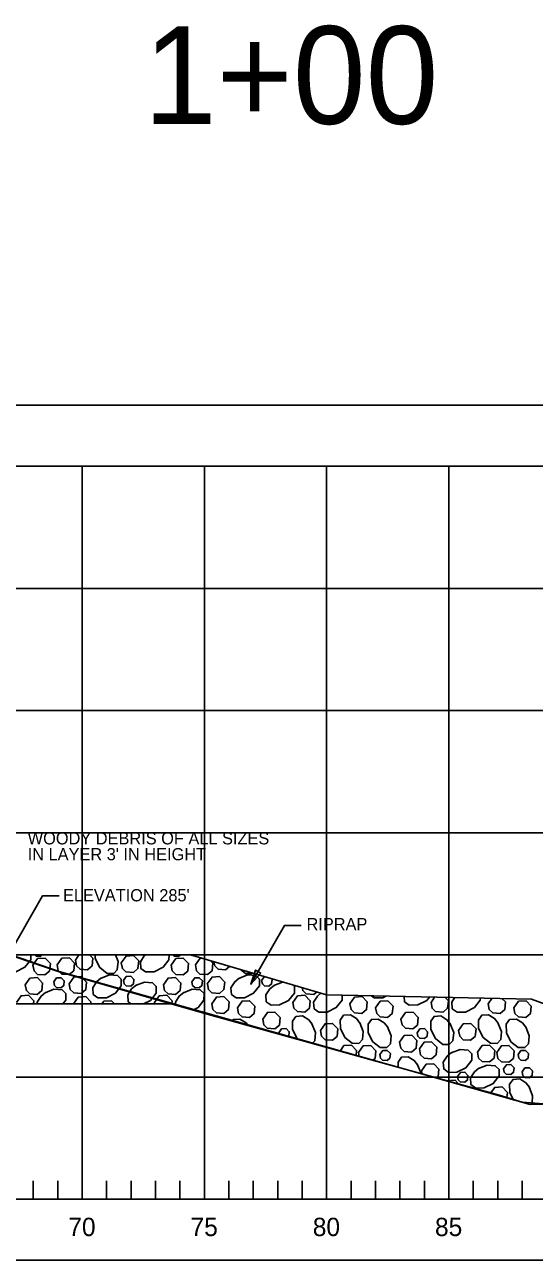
# Model space of a CAD drawing. Extents: x 1578769 to 1579225, y 724002 to 724828.
# Drawn here: x 1578892.8 to 1578913.6, y 724249.6 to 724300.2 of the extents above; entities that cross this region are included whole.
import ezdxf

# ---------------------------------------------------------------- set-up
doc = ezdxf.new("R2010")
doc.units = 0
for name, color, linetype in [('1', 7, 'Continuous'), ('Default', 7, 'Continuous'), ('Old_Level_1', 7, 'Continuous'), ('Old_Level_41', 7, 'Continuous'), ('Old_Level_42', 7, 'Continuous'), ('R_Exist Surface', 7, 'Continuous'), ('R_Rip-Rap', 7, 'Continuous')]:
    doc.layers.add(name, color=color, linetype=linetype)

msp = doc.modelspace()

# ---------------------------------------------------------------- linework, layer by layer
at = {"layer": '1'}
for points in [[(1578892.141, 724262.141), (1578893.509, 724264.554), (1578894.194, 724264.554)], [(1578902.042, 724260.935), (1578903.41, 724263.349), (1578904.095, 724263.349)]]:
    msp.add_lwpolyline(points, dxfattribs=at)
msp.add_lwpolyline([(1578902.442, 724261.398), (1578902.042, 724260.935), (1578902.233, 724261.516)], close=True, dxfattribs=at)
at = {"layer": 'Default'}
msp.add_line((1578825.136, 724252.141), (1579225.136, 724252.141), dxfattribs=at)
msp.add_lwpolyline([(1578826.025, 724272.503), (1578843.356, 724272.54), (1578848.216, 724272.563), (1578852.656, 724272.595), (1578873.806, 724272.679), (1578875.706, 724271.556), (1578889.515, 724263.067), (1578894.196, 724261.454), (1578913.456, 724256.023), (1578914.486, 724256.05), (1578915.035, 724256.065), (1578992.496, 724256.633), (1578992.515, 724256.633), (1578992.566, 724256.634), (1578992.736, 724256.639), (1578993.706, 724256.668), (1579090.356, 724259.528), (1579113.086, 724262.229), (1579131.176, 724264.398), (1579155.015, 724266.722), (1579177.006, 724269.229), (1579191.525, 724270.885)], dxfattribs=at)
at = {"layer": 'Old_Level_1'}
for points in [[(1578820.135, 724284.641), (1578927.635, 724284.641), (1578927.635, 724249.641), (1578820.135, 724249.641)], [(1578825.135, 724282.141), (1578925.135, 724282.141), (1578925.135, 724252.141), (1578825.135, 724252.141)]]:
    msp.add_lwpolyline(points, close=True, dxfattribs=at)
at = {"layer": 'Old_Level_41'}
for p, q in [((1578895.135, 724282.141), (1578895.135, 724252.141)), ((1578900.135, 724252.141), (1578900.135, 724282.141)), ((1578905.135, 724282.141), (1578905.135, 724252.141)), ((1578910.135, 724252.141), (1578910.135, 724282.141))]:
    msp.add_line(p, q, dxfattribs=at)
for points in [[(1578925.135, 724277.141), (1578825.135, 724277.141)], [(1578925.135, 724272.141), (1578825.135, 724272.141)], [(1578825.135, 724267.141), (1578925.135, 724267.141)], [(1578925.135, 724262.141), (1578825.135, 724262.141)], [(1578825.135, 724257.141), (1578925.135, 724257.141)]]:
    msp.add_lwpolyline(points, dxfattribs=at)
at = {"layer": 'Old_Level_42'}
for p, q in [((1578893.135, 724252.891), (1578893.135, 724252.141)), ((1578894.135, 724252.891), (1578894.135, 724252.141)), ((1578896.135, 724252.891), (1578896.135, 724252.141)), ((1578897.135, 724252.891), (1578897.135, 724252.141)), ((1578898.135, 724252.891), (1578898.135, 724252.141)), ((1578899.135, 724252.891), (1578899.135, 724252.141)), ((1578901.135, 724252.891), (1578901.135, 724252.141)), ((1578902.135, 724252.891), (1578902.135, 724252.141)), ((1578903.135, 724252.891), (1578903.135, 724252.141)), ((1578904.135, 724252.891), (1578904.135, 724252.141)), ((1578906.135, 724252.891), (1578906.135, 724252.141)), ((1578907.135, 724252.891), (1578907.135, 724252.141)), ((1578908.135, 724252.891), (1578908.135, 724252.141)), ((1578909.135, 724252.891), (1578909.135, 724252.141)), ((1578911.135, 724252.891), (1578911.135, 724252.141)), ((1578912.135, 724252.891), (1578912.135, 724252.141)), ((1578913.135, 724252.891), (1578913.135, 724252.141))]:
    msp.add_line(p, q, dxfattribs=at)
at = {"layer": 'R_Exist Surface'}
msp.add_lwpolyline([(1578826.062, 724272.509), (1578843.255, 724272.529), (1578855.204, 724272.649), (1578859.177, 724272.597), (1578872.167, 724272.617), (1578873.087, 724272.657), (1578874.163, 724272.457), (1578875.161, 724271.898), (1578886.138, 724265.225), (1578890.363, 724262.7), (1578891.18, 724262.468), (1578894.233, 724261.427), (1578900.147, 724259.744), (1578907.197, 724257.773), (1578912.15, 724256.411), (1578913.135, 724256.113), (1578914.178, 724256.033), (1578918.136, 724256.056), (1578925.136, 724256.105)], dxfattribs=at)
at = {"layer": 'R_Rip-Rap'}
for p, q in [((1578899.572, 724262.141), (1578888.226, 724262.141)), ((1578894.858, 724261.93), (1578895.006, 724262.141)), ((1578905.135, 724260.499), (1578899.572, 724262.141)), ((1578902.478, 724261.094), (1578902.588, 724261.251)), ((1578888.226, 724260.134), (1578898.778, 724260.134)), ((1578894.784, 724260.134), (1578894.783, 724260.142)), ((1578898.111, 724260.134), (1578898.099, 724260.196)), ((1578913.512, 724260.324), (1578905.135, 724260.499)), ((1578909.406, 724260.196), (1578909.554, 724260.407)), ((1578911.743, 724260.142), (1578911.894, 724260.357)), ((1578924.962, 724256.104), (1578913.512, 724260.324)), ((1578903.192, 724258.893), (1578903.181, 724258.95)), ((1578906.473, 724257.981), (1578906.441, 724258.143)), ((1578909.042, 724257.267), (1578909.018, 724257.391))]:
    msp.add_line(p, q, dxfattribs=at)
for points in [[(1578893.036, 724262.141), (1578893.033, 724261.938), (1578892.795, 724261.634), (1578892.427, 724261.45), (1578892.08, 724261.444), (1578891.885, 724261.582), (1578891.866, 724261.859), (1578892.025, 724262.106), (1578892.068, 724262.141)], [(1578893.502, 724262.141), (1578893.43, 724262.08), (1578893.248, 724262.094), (1578893.2, 724262.141)], [(1578895.434, 724262.141), (1578895.57, 724262), (1578895.539, 724261.69), (1578895.35, 724261.533), (1578895.047, 724261.555), (1578894.904, 724261.693), (1578894.858, 724261.93)], [(1578896.493, 724262.141), (1578896.603, 724261.864), (1578896.574, 724261.533), (1578896.425, 724261.377), (1578896.157, 724261.382), (1578895.853, 724261.62), (1578895.669, 724261.988), (1578895.666, 724262.141)], [(1578896.737, 724261.82), (1578896.929, 724262.093), (1578897.236, 724262.111), (1578897.449, 724261.89), (1578897.418, 724261.58), (1578897.229, 724261.422), (1578896.926, 724261.444), (1578896.784, 724261.582), (1578896.737, 724261.82)], [(1578898.69, 724262.141), (1578898.686, 724261.938), (1578898.448, 724261.634), (1578898.08, 724261.45), (1578897.733, 724261.444), (1578897.538, 724261.582), (1578897.52, 724261.859), (1578897.678, 724262.106), (1578897.722, 724262.141)], [(1578899.156, 724262.141), (1578899.083, 724262.08), (1578898.902, 724262.094), (1578898.853, 724262.141)], [(1578893.122, 724261.719), (1578893.314, 724261.992), (1578893.621, 724262.009), (1578893.834, 724261.788), (1578893.803, 724261.478), (1578893.614, 724261.321), (1578893.311, 724261.343), (1578893.168, 724261.481), (1578893.122, 724261.718)], [(1578894.113, 724261.73), (1578894.305, 724262.003), (1578894.612, 724262.021), (1578894.825, 724261.8), (1578894.794, 724261.49), (1578894.605, 724261.332), (1578894.302, 724261.354), (1578894.159, 724261.492), (1578894.113, 724261.73)], [(1578898.775, 724261.719), (1578898.968, 724261.992), (1578899.274, 724262.009), (1578899.487, 724261.788), (1578899.457, 724261.478), (1578899.267, 724261.321), (1578898.964, 724261.343), (1578898.822, 724261.481), (1578898.776, 724261.718)], [(1578899.766, 724261.73), (1578899.959, 724262.003), (1578900.025, 724262.007)], [(1578900.379, 724261.902), (1578900.478, 724261.8), (1578900.448, 724261.49), (1578900.258, 724261.332), (1578899.955, 724261.354), (1578899.813, 724261.492), (1578899.767, 724261.73)], [(1578901.168, 724261.67), (1578901.003, 724261.533), (1578900.7, 724261.555), (1578900.558, 724261.693), (1578900.525, 724261.859)], [(1578892.807, 724260.918), (1578892.999, 724261.192), (1578893.306, 724261.209), (1578893.519, 724260.988), (1578893.488, 724260.678), (1578893.299, 724260.521), (1578892.996, 724260.543), (1578892.853, 724260.681), (1578892.807, 724260.918)], [(1578893.972, 724261.031), (1578894.088, 724261.195), (1578894.272, 724261.205), (1578894.4, 724261.073), (1578894.381, 724260.887), (1578894.268, 724260.792), (1578894.086, 724260.805), (1578894, 724260.888), (1578893.973, 724261.031)], [(1578894.602, 724260.96), (1578894.794, 724261.233), (1578895.101, 724261.251), (1578895.314, 724261.03), (1578895.283, 724260.72), (1578895.094, 724260.562), (1578894.791, 724260.584), (1578894.648, 724260.722), (1578894.602, 724260.96)], [(1578895.891, 724261.178), (1578896.25, 724261.321), (1578896.58, 724261.292), (1578896.737, 724261.143), (1578896.732, 724260.875), (1578896.494, 724260.571), (1578896.126, 724260.387), (1578895.779, 724260.381), (1578895.584, 724260.52), (1578895.566, 724260.796), (1578895.724, 724261.043), (1578895.905, 724261.188)], [(1578896.825, 724261.094), (1578896.94, 724261.258), (1578897.124, 724261.268), (1578897.252, 724261.136), (1578897.233, 724260.95), (1578897.12, 724260.855), (1578896.938, 724260.868), (1578896.853, 724260.951), (1578896.825, 724261.094)], [(1578898.46, 724260.918), (1578898.653, 724261.192), (1578898.959, 724261.209), (1578899.172, 724260.988), (1578899.142, 724260.678), (1578898.952, 724260.521), (1578898.649, 724260.543), (1578898.507, 724260.681), (1578898.461, 724260.918)], [(1578899.626, 724261.031), (1578899.741, 724261.195), (1578899.925, 724261.205), (1578900.053, 724261.073), (1578900.035, 724260.887), (1578899.921, 724260.792), (1578899.739, 724260.805), (1578899.654, 724260.888), (1578899.626, 724261.031)], [(1578900.255, 724260.96), (1578900.447, 724261.233), (1578900.754, 724261.251), (1578900.967, 724261.03), (1578900.936, 724260.72), (1578900.747, 724260.562), (1578900.444, 724260.584), (1578900.302, 724260.722), (1578900.256, 724260.96)], [(1578901.544, 724261.178), (1578901.904, 724261.321), (1578902.234, 724261.292), (1578902.391, 724261.143), (1578902.386, 724260.875), (1578902.148, 724260.571), (1578901.78, 724260.387), (1578901.433, 724260.381), (1578901.238, 724260.52), (1578901.219, 724260.796), (1578901.377, 724261.043), (1578901.559, 724261.188)], [(1578902.097, 724261.396), (1578902.079, 724261.377), (1578901.811, 724261.382), (1578901.609, 724261.54)], [(1578902.876, 724261.166), (1578902.905, 724261.136), (1578902.887, 724260.95), (1578902.773, 724260.855), (1578902.591, 724260.868), (1578902.506, 724260.951), (1578902.478, 724261.094)], [(1578893.301, 724260.134), (1578893.296, 724260.21), (1578893.454, 724260.457), (1578893.636, 724260.602)], [(1578893.621, 724260.593), (1578893.98, 724260.735), (1578894.311, 724260.707), (1578894.467, 724260.558), (1578894.462, 724260.29), (1578894.34, 724260.134)], [(1578897.143, 724260.134), (1578897.016, 724260.225), (1578896.997, 724260.501), (1578897.156, 724260.748), (1578897.337, 724260.893)], [(1578897.322, 724260.883), (1578897.682, 724261.026), (1578898.012, 724260.997), (1578898.169, 724260.848), (1578898.164, 724260.58), (1578897.926, 724260.276), (1578897.642, 724260.134)], [(1578898.958, 724260.083), (1578898.949, 724260.21), (1578899.108, 724260.457), (1578899.289, 724260.602)], [(1578899.275, 724260.593), (1578899.634, 724260.735), (1578899.964, 724260.707), (1578900.121, 724260.558), (1578900.116, 724260.29), (1578899.878, 724259.986), (1578899.668, 724259.881)], [(1578903.764, 724260.904), (1578903.822, 724260.848), (1578903.817, 724260.58), (1578903.579, 724260.276), (1578903.211, 724260.092), (1578902.864, 724260.086), (1578902.669, 724260.225), (1578902.651, 724260.501), (1578902.809, 724260.748), (1578902.99, 724260.893)], [(1578902.976, 724260.883), (1578903.335, 724261.026), (1578903.356, 724261.024)], [(1578904.725, 724260.62), (1578904.606, 724260.521), (1578904.303, 724260.543), (1578904.16, 724260.681), (1578904.138, 724260.793)], [(1578892.446, 724260.196), (1578892.638, 724260.469), (1578892.944, 724260.486), (1578893.158, 724260.265), (1578893.144, 724260.134)], [(1578894.783, 724260.142), (1578894.975, 724260.415), (1578895.281, 724260.433), (1578895.495, 724260.212), (1578895.487, 724260.134)], [(1578895.945, 724260.134), (1578896.025, 724260.248), (1578896.332, 724260.265), (1578896.458, 724260.134)], [(1578898.099, 724260.196), (1578898.291, 724260.469), (1578898.598, 724260.486), (1578898.811, 724260.265), (1578898.797, 724260.128)], [(1578900.436, 724260.142), (1578900.628, 724260.415), (1578900.935, 724260.433), (1578901.148, 724260.212), (1578901.117, 724259.902), (1578900.928, 724259.744), (1578900.625, 724259.766), (1578900.483, 724259.904), (1578900.436, 724260.142)], [(1578901.486, 724259.975), (1578901.678, 724260.248), (1578901.985, 724260.265), (1578902.198, 724260.044), (1578902.167, 724259.735), (1578901.978, 724259.577), (1578901.675, 724259.599), (1578901.533, 724259.737), (1578901.486, 724259.975)], [(1578903.752, 724260.196), (1578903.945, 724260.469), (1578904.251, 724260.486), (1578904.464, 724260.265), (1578904.434, 724259.956), (1578904.244, 724259.798), (1578903.941, 724259.82), (1578903.799, 724259.958), (1578903.753, 724260.196)], [(1578905.773, 724260.486), (1578905.769, 724260.29), (1578905.531, 724259.986), (1578905.163, 724259.802), (1578904.816, 724259.795), (1578904.621, 724259.934), (1578904.603, 724260.21), (1578904.761, 724260.457), (1578904.9, 724260.569)], [(1578906.09, 724260.142), (1578906.282, 724260.415), (1578906.588, 724260.433), (1578906.801, 724260.212), (1578906.771, 724259.902), (1578906.581, 724259.744), (1578906.278, 724259.766), (1578906.136, 724259.904), (1578906.09, 724260.142)], [(1578907.556, 724260.448), (1578907.433, 724260.387), (1578907.086, 724260.381), (1578906.974, 724260.461)], [(1578907.14, 724259.975), (1578907.332, 724260.248), (1578907.638, 724260.265), (1578907.852, 724260.044), (1578907.821, 724259.735), (1578907.631, 724259.577), (1578907.329, 724259.599), (1578907.186, 724259.737), (1578907.14, 724259.975)], [(1578909.338, 724260.411), (1578909.232, 724260.276), (1578908.865, 724260.092), (1578908.518, 724260.086), (1578908.323, 724260.225), (1578908.309, 724260.433)], [(1578909.99, 724260.397), (1578910.118, 724260.265), (1578910.087, 724259.956), (1578909.898, 724259.798), (1578909.595, 724259.82), (1578909.452, 724259.958), (1578909.406, 724260.196)], [(1578911.424, 724260.367), (1578911.423, 724260.29), (1578911.185, 724259.986), (1578910.817, 724259.802), (1578910.47, 724259.795), (1578910.275, 724259.934), (1578910.256, 724260.21), (1578910.371, 724260.389)], [(1578912.323, 724260.348), (1578912.455, 724260.212), (1578912.424, 724259.902), (1578912.235, 724259.744), (1578911.932, 724259.766), (1578911.789, 724259.904), (1578911.743, 724260.142)], [(1578912.793, 724259.975), (1578912.985, 724260.248), (1578913.292, 724260.265), (1578913.505, 724260.044), (1578913.474, 724259.735), (1578913.285, 724259.577), (1578912.982, 724259.599), (1578912.84, 724259.737), (1578912.793, 724259.975)], [(1578900.366, 724259.683), (1578900.453, 724259.689), (1578900.537, 724259.635)], [(1578902.521, 724259.51), (1578902.713, 724259.783), (1578903.019, 724259.801), (1578903.233, 724259.58), (1578903.202, 724259.27), (1578903.012, 724259.112), (1578902.71, 724259.134), (1578902.567, 724259.273), (1578902.521, 724259.51)], [(1578903.983, 724258.672), (1578903.93, 724258.714), (1578903.746, 724259.082), (1578903.74, 724259.429), (1578903.878, 724259.624), (1578904.155, 724259.642), (1578904.402, 724259.484), (1578904.546, 724259.303)], [(1578906.489, 724259.364), (1578906.632, 724259.004), (1578906.603, 724258.674), (1578906.454, 724258.517), (1578906.186, 724258.522), (1578905.882, 724258.76), (1578905.698, 724259.128), (1578905.692, 724259.475), (1578905.83, 724259.67), (1578906.107, 724259.689), (1578906.354, 724259.531), (1578906.498, 724259.349)], [(1578908.174, 724259.51), (1578908.366, 724259.783), (1578908.673, 724259.801), (1578908.886, 724259.58), (1578908.855, 724259.27), (1578908.666, 724259.112), (1578908.363, 724259.134), (1578908.221, 724259.273), (1578908.174, 724259.51)], [(1578910.19, 724259.317), (1578910.333, 724258.958), (1578910.304, 724258.628), (1578910.155, 724258.471), (1578909.887, 724258.476), (1578909.583, 724258.714), (1578909.399, 724259.082), (1578909.393, 724259.429), (1578909.532, 724259.624), (1578909.808, 724259.642), (1578910.055, 724259.484), (1578910.2, 724259.303)], [(1578912.143, 724259.364), (1578912.285, 724259.004), (1578912.257, 724258.674), (1578912.107, 724258.517), (1578911.84, 724258.522), (1578911.535, 724258.76), (1578911.351, 724259.128), (1578911.345, 724259.475), (1578911.484, 724259.67), (1578911.76, 724259.689), (1578912.007, 724259.531), (1578912.152, 724259.349)], [(1578901.269, 724259.431), (1578901.316, 724259.496), (1578901.592, 724259.515), (1578901.839, 724259.356), (1578901.926, 724259.247)], [(1578903.181, 724258.95), (1578903.296, 724259.114), (1578903.48, 724259.125), (1578903.608, 724258.992), (1578903.589, 724258.806), (1578903.568, 724258.788)], [(1578904.537, 724259.317), (1578904.68, 724258.958), (1578904.651, 724258.628), (1578904.545, 724258.516)], [(1578904.882, 724259.045), (1578905.074, 724259.319), (1578905.381, 724259.336), (1578905.594, 724259.115), (1578905.563, 724258.805), (1578905.374, 724258.648), (1578905.071, 724258.67), (1578904.929, 724258.808), (1578904.882, 724259.045)], [(1578907.628, 724259.189), (1578907.77, 724258.83), (1578907.742, 724258.5), (1578907.593, 724258.343), (1578907.325, 724258.348), (1578907.021, 724258.586), (1578906.837, 724258.954), (1578906.831, 724259.301), (1578906.969, 724259.496), (1578907.245, 724259.515), (1578907.493, 724259.356), (1578907.637, 724259.175)], [(1578908.834, 724258.95), (1578908.949, 724259.114), (1578909.133, 724259.125), (1578909.261, 724258.992), (1578909.243, 724258.806), (1578909.129, 724258.712), (1578908.947, 724258.725), (1578908.862, 724258.808), (1578908.834, 724258.95)], [(1578910.536, 724259.045), (1578910.728, 724259.319), (1578911.034, 724259.336), (1578911.248, 724259.115), (1578911.217, 724258.805), (1578911.027, 724258.648), (1578910.724, 724258.67), (1578910.582, 724258.808), (1578910.536, 724259.045)], [(1578913.281, 724259.189), (1578913.424, 724258.83), (1578913.395, 724258.5), (1578913.246, 724258.343), (1578912.978, 724258.348), (1578912.674, 724258.586), (1578912.49, 724258.954), (1578912.484, 724259.301), (1578912.623, 724259.496), (1578912.899, 724259.515), (1578913.146, 724259.356), (1578913.291, 724259.175)], [(1578908.12, 724258.561), (1578908.312, 724258.834), (1578908.619, 724258.852), (1578908.832, 724258.631), (1578908.801, 724258.321), (1578908.612, 724258.164), (1578908.309, 724258.186), (1578908.167, 724258.324), (1578908.121, 724258.561)], [(1578908.932, 724258.29), (1578909.124, 724258.563), (1578909.431, 724258.581), (1578909.644, 724258.36), (1578909.613, 724258.05), (1578909.424, 724257.892), (1578909.121, 724257.914), (1578908.978, 724258.052), (1578908.932, 724258.29)], [(1578905.683, 724258.2), (1578905.843, 724258.428), (1578906.15, 724258.445), (1578906.363, 724258.224), (1578906.342, 724258.017)], [(1578906.441, 724258.143), (1578906.633, 724258.416), (1578906.94, 724258.434), (1578907.153, 724258.213), (1578907.122, 724257.903), (1578907.03, 724257.826)], [(1578907.315, 724258.059), (1578907.43, 724258.222), (1578907.614, 724258.233), (1578907.742, 724258.1), (1578907.724, 724257.915), (1578907.61, 724257.82), (1578907.428, 724257.833), (1578907.343, 724257.916), (1578907.315, 724258.058)], [(1578910.233, 724258.13), (1578910.592, 724258.272), (1578910.922, 724258.243), (1578911.079, 724258.094), (1578911.074, 724257.826), (1578910.836, 724257.522), (1578910.468, 724257.338), (1578910.121, 724257.332), (1578909.926, 724257.471), (1578909.908, 724257.747), (1578910.066, 724257.994), (1578910.247, 724258.139)], [(1578911.304, 724258.155), (1578911.496, 724258.428), (1578911.803, 724258.445), (1578912.016, 724258.224), (1578911.985, 724257.915), (1578911.796, 724257.757), (1578911.493, 724257.779), (1578911.351, 724257.917), (1578911.304, 724258.154)], [(1578912.094, 724258.143), (1578912.286, 724258.416), (1578912.593, 724258.434), (1578912.806, 724258.213), (1578912.776, 724257.903), (1578912.586, 724257.745), (1578912.283, 724257.767), (1578912.141, 724257.905), (1578912.095, 724258.143)], [(1578912.968, 724258.059), (1578913.084, 724258.222), (1578913.268, 724258.233), (1578913.396, 724258.1), (1578913.377, 724257.915), (1578913.263, 724257.82), (1578913.082, 724257.833), (1578912.996, 724257.916), (1578912.968, 724258.058)], [(1578908.061, 724257.54), (1578908.057, 724257.755), (1578908.195, 724257.951), (1578908.472, 724257.969), (1578908.719, 724257.811), (1578908.863, 724257.629)], [(1578908.854, 724257.644), (1578908.997, 724257.285), (1578908.996, 724257.28)], [(1578909.017, 724257.391), (1578909.21, 724257.664), (1578909.516, 724257.682), (1578909.729, 724257.461), (1578909.699, 724257.151), (1578909.639, 724257.102)], [(1578911.348, 724257.488), (1578911.707, 724257.63), (1578912.037, 724257.602), (1578912.194, 724257.452), (1578912.189, 724257.185), (1578911.951, 724256.88), (1578911.583, 724256.696), (1578911.236, 724256.69), (1578911.041, 724256.829), (1578911.022, 724257.105), (1578911.181, 724257.352), (1578911.362, 724257.497)], [(1578912.374, 724257.482), (1578912.489, 724257.646), (1578912.673, 724257.657), (1578912.801, 724257.524), (1578912.783, 724257.338), (1578912.669, 724257.243), (1578912.487, 724257.257), (1578912.402, 724257.34), (1578912.374, 724257.482)], [(1578910.491, 724257.167), (1578910.607, 724257.331), (1578910.791, 724257.341), (1578910.919, 724257.209), (1578910.9, 724257.023), (1578910.786, 724256.928), (1578910.605, 724256.941), (1578910.519, 724257.024), (1578910.492, 724257.167)], [(1578912.773, 724256.215), (1578912.629, 724256.502), (1578912.623, 724256.849), (1578912.762, 724257.044), (1578913.038, 724257.063), (1578913.285, 724256.904), (1578913.43, 724256.723)], [(1578913.13, 724257.347), (1578913.246, 724257.511), (1578913.43, 724257.521), (1578913.558, 724257.389), (1578913.539, 724257.203), (1578913.426, 724257.108), (1578913.244, 724257.122), (1578913.158, 724257.204), (1578913.131, 724257.347)], [(1578910.177, 724256.95), (1578910.21, 724256.998), (1578910.394, 724257.008), (1578910.522, 724256.875), (1578910.52, 724256.853)], [(1578911.842, 724256.479), (1578912.01, 724256.718), (1578912.317, 724256.736), (1578912.53, 724256.514), (1578912.508, 724256.29)], [(1578913.421, 724256.737), (1578913.563, 724256.378), (1578913.538, 724256.082)]]:
    msp.add_lwpolyline(points, dxfattribs=at)

# ---------------------------------------------------------------- texts
at = {"layer": '1'}
for s, height, p in [('WOODY DEBRIS OF ALL SIZES', 0.5, (1578892.907, 724266.662)), ("IN LAYER 3' IN HEIGHT", 0.5, (1578892.907, 724266.011)), ("ELEVATION 285'", 0.5, (1578894.352, 724264.331)), ('RIPRAP', 0.5, (1578904.313, 724263.149)), ('70', 0.75, (1578894.569, 724250.631)), ('75', 0.75, (1578899.569, 724250.631)), ('80', 0.75, (1578904.569, 724250.631)), ('85', 0.75, (1578909.569, 724250.631))]:
    msp.add_text(s, height=height, dxfattribs=at).set_placement(p)
at = {"layer": 'Default'}
msp.add_text('1+00', height=4, dxfattribs=at).set_placement((1578897.659, 724296.15))

doc.saveas('drawing.dxf')
